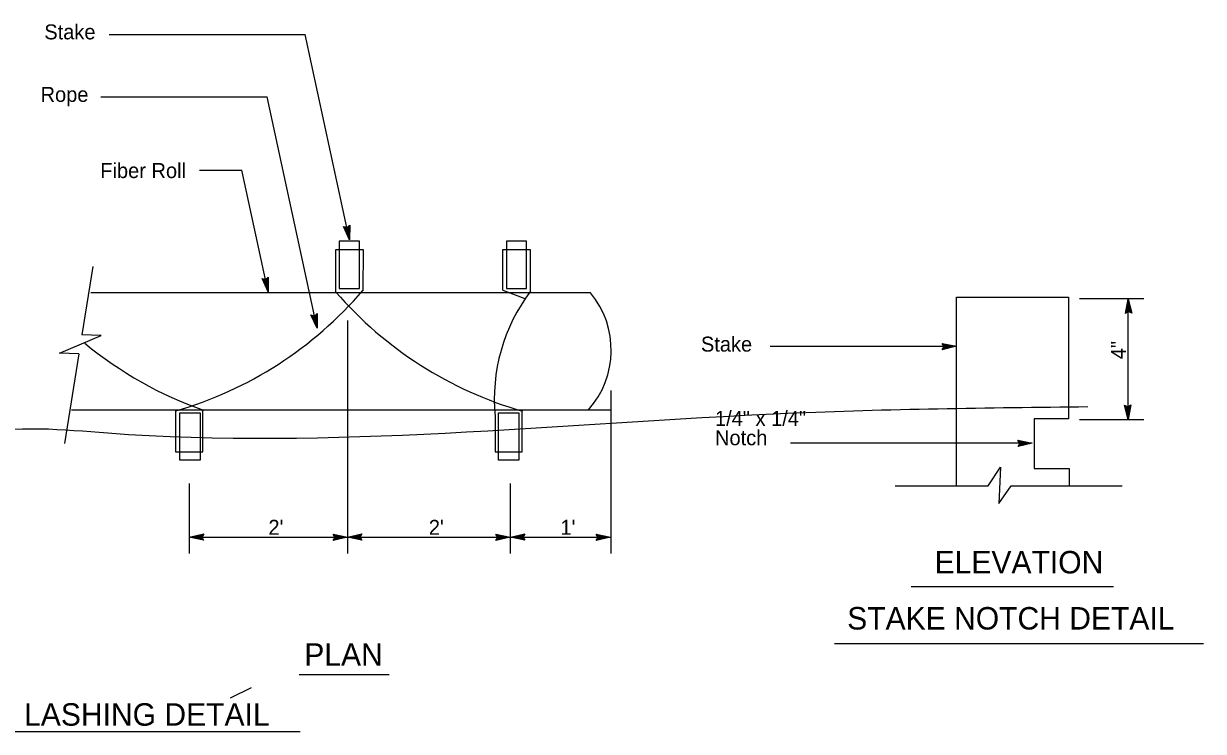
# Model space of a CAD drawing. Extents: x 6707415 to 6708768, y 1869893 to 1870831.
# Drawn here: x 6707688.3 to 6708160.7, y 1870548 to 1870831.3 of the extents above; entities that cross this region are included whole.
import ezdxf

# ---------------------------------------------------------------- set-up
doc = ezdxf.new("R2010")
doc.units = 0
for name, color, linetype in [('56 Stg 3 Anno', 7, 'Continuous'), ('57 Undefined', 7, 'Continuous'), ('60 Nongeo Data', 7, 'Continuous')]:
    doc.layers.add(name, color=color, linetype=linetype)

msp = doc.modelspace()

# ---------------------------------------------------------------- linework, layer by layer
at = {"layer": '56 Stg 3 Anno'}
for p, q in [((6707722.63, 1870827.01), (6707801.07, 1870827.01)), ((6707818.84, 1870744.79), (6707801.07, 1870827.01)), ((6707719.2, 1870801.99), (6707785.82, 1870801.99)), ((6707805.84, 1870709.37), (6707785.82, 1870801.99)), ((6707758.79, 1870772.63), (6707775.73, 1870772.63)), ((6707786.26, 1870723.94), (6707775.73, 1870772.63)), ((6707818.84, 1870744.79), (6707816.38, 1870750.15)), ((6707816.38, 1870750.15), (6707816.38, 1870750.15)), ((6707816.38, 1870750.15), (6707817.79, 1870749.67)), ((6707818.56, 1870746.1), (6707816.77, 1870750.01)), ((6707817.79, 1870749.67), (6707818.89, 1870750.69)), ((6707818.31, 1870750.13), (6707818.29, 1870747.39)), ((6707818.6, 1870750.42), (6707818.56, 1870746.09)), ((6707818.89, 1870750.69), (6707818.84, 1870744.79)), ((6707818.89, 1870750.69), (6707818.89, 1870750.69)), ((6707818.29, 1870747.39), (6707817.13, 1870749.91)), ((6707818.01, 1870748.68), (6707817.51, 1870749.76)), ((6707818.02, 1870749.89), (6707818.01, 1870748.68)), ((6707818.84, 1870744.79), (6707818.84, 1870744.79)), ((6707786.26, 1870723.94), (6707783.8, 1870729.3)), ((6707783.8, 1870729.3), (6707783.8, 1870729.3)), ((6707783.8, 1870729.3), (6707785.21, 1870728.82)), ((6707785.97, 1870725.24), (6707784.18, 1870729.15)), ((6707785.7, 1870726.53), (6707784.55, 1870729.06)), ((6707785.43, 1870727.83), (6707784.93, 1870728.91)), ((6707785.21, 1870728.82), (6707786.31, 1870729.84)), ((6707785.43, 1870729.04), (6707785.43, 1870727.83)), ((6707785.72, 1870729.27), (6707785.7, 1870726.53)), ((6707786.02, 1870729.57), (6707785.98, 1870725.23)), ((6707786.31, 1870729.84), (6707786.26, 1870723.94)), ((6707786.31, 1870729.84), (6707786.31, 1870729.84)), ((6707786.26, 1870723.94), (6707786.26, 1870723.94)), ((6708111.13, 1870721.29), (6708136.89, 1870721.29)), ((6708129.49, 1870715.26), (6708130.61, 1870721.06)), ((6708129.83, 1870715.48), (6708130.65, 1870719.73)), ((6708130.16, 1870715.72), (6708130.68, 1870718.41)), ((6708130.49, 1870715.89), (6708130.72, 1870717.08)), ((6708130.61, 1870672.85), (6708130.61, 1870721.06)), ((6708130.61, 1870721.06), (6708130.61, 1870721.06)), ((6708130.61, 1870721.06), (6708132.05, 1870715.34)), ((6708130.65, 1870719.72), (6708131.7, 1870715.55)), ((6708130.68, 1870718.41), (6708131.36, 1870715.71)), ((6708130.72, 1870717.08), (6708131.01, 1870715.93)), ((6707805.84, 1870709.37), (6707803.38, 1870714.73)), ((6707803.38, 1870714.73), (6707803.38, 1870714.73)), ((6707803.38, 1870714.73), (6707804.79, 1870714.25)), ((6707805.56, 1870710.68), (6707803.77, 1870714.59)), ((6707805.28, 1870711.97), (6707804.13, 1870714.49)), ((6707805.01, 1870713.26), (6707804.51, 1870714.34)), ((6707804.79, 1870714.25), (6707805.89, 1870715.27)), ((6707805.02, 1870714.47), (6707805.01, 1870713.26)), ((6707805.31, 1870714.71), (6707805.28, 1870711.97)), ((6707805.6, 1870715), (6707805.56, 1870710.67)), ((6707805.89, 1870715.27), (6707805.84, 1870709.37)), ((6707805.89, 1870715.27), (6707805.89, 1870715.27)), ((6707818.04, 1870712.48), (6707818.04, 1870619.14)), ((6708130.75, 1870716.07), (6708129.49, 1870715.26)), ((6708129.49, 1870715.26), (6708129.49, 1870715.26)), ((6708132.05, 1870715.34), (6708130.75, 1870716.07)), ((6708132.05, 1870715.34), (6708132.05, 1870715.34)), ((6707805.84, 1870709.37), (6707805.84, 1870709.37)), ((6708056.91, 1870702.01), (6708056.1, 1870703.27)), ((6708056.1, 1870703.27), (6708056.1, 1870703.27)), ((6708056.1, 1870703.27), (6708061.9, 1870702.15)), ((6708056.32, 1870702.94), (6708060.57, 1870702.12)), ((6707987.21, 1870702.15), (6708061.9, 1870702.15)), ((6708061.9, 1870702.15), (6708056.18, 1870700.71)), ((6708056.18, 1870700.71), (6708056.91, 1870702.01)), ((6708056.18, 1870700.71), (6708056.18, 1870700.71)), ((6708060.56, 1870702.11), (6708056.39, 1870701.06)), ((6708056.55, 1870702.6), (6708059.24, 1870702.08)), ((6708059.24, 1870702.08), (6708056.55, 1870701.4)), ((6708056.73, 1870702.27), (6708057.92, 1870702.04)), ((6708057.92, 1870702.04), (6708056.77, 1870701.75)), ((6708061.9, 1870702.15), (6708061.9, 1870702.15)), ((6707923.49, 1870684.37), (6707923.49, 1870619.14)), ((6708130.61, 1870672.85), (6708129.17, 1870678.57)), ((6708129.17, 1870678.57), (6708129.17, 1870678.57)), ((6708129.17, 1870678.57), (6708130.46, 1870677.84)), ((6708130.57, 1870674.19), (6708129.52, 1870678.36)), ((6708130.53, 1870675.5), (6708129.85, 1870678.2)), ((6708130.5, 1870676.83), (6708130.21, 1870677.98)), ((6708130.46, 1870677.84), (6708131.73, 1870678.65)), ((6708130.73, 1870678.02), (6708130.5, 1870676.83)), ((6708131.05, 1870678.2), (6708130.53, 1870675.5)), ((6708131.39, 1870678.43), (6708130.57, 1870674.18)), ((6708131.73, 1870678.65), (6708130.61, 1870672.85)), ((6708131.73, 1870678.65), (6708131.73, 1870678.65)), ((6708111.13, 1870672.85), (6708136.89, 1870672.85)), ((6708130.61, 1870672.85), (6708130.61, 1870672.85)), ((6708092.23, 1870663.4), (6707995.46, 1870663.4)), ((6708087.24, 1870663.25), (6708086.43, 1870664.52)), ((6708086.43, 1870664.52), (6708086.43, 1870664.52)), ((6708086.43, 1870664.52), (6708092.23, 1870663.4)), ((6708092.23, 1870663.4), (6708086.51, 1870661.96)), ((6708086.51, 1870661.96), (6708087.24, 1870663.25)), ((6708086.51, 1870661.96), (6708086.51, 1870661.96)), ((6708086.65, 1870664.18), (6708090.9, 1870663.36)), ((6708090.89, 1870663.36), (6708086.72, 1870662.31)), ((6708086.88, 1870663.84), (6708089.57, 1870663.32)), ((6708089.57, 1870663.32), (6708086.88, 1870662.64)), ((6708087.06, 1870663.52), (6708088.25, 1870663.29)), ((6708088.25, 1870663.29), (6708087.1, 1870663)), ((6708092.23, 1870663.4), (6708092.23, 1870663.4)), ((6707754.67, 1870647.14), (6707754.67, 1870619.14)), ((6707883.15, 1870647.14), (6707883.15, 1870619.14)), ((6707754.67, 1870625.78), (6707760.44, 1870627.03)), ((6707754.67, 1870625.78), (6707818.04, 1870625.78)), ((6707760.42, 1870624.47), (6707754.67, 1870625.78)), ((6707754.67, 1870625.78), (6707754.67, 1870625.78)), ((6707760.22, 1870624.81), (6707755.99, 1870625.77)), ((6707756.01, 1870625.78), (6707760.21, 1870626.69)), ((6707757.32, 1870625.76), (6707760.04, 1870626.35)), ((6707760, 1870625.16), (6707757.32, 1870625.76)), ((6707758.65, 1870625.76), (6707759.81, 1870626.01)), ((6707759.83, 1870625.49), (6707758.65, 1870625.76)), ((6707760.44, 1870627.03), (6707759.66, 1870625.76)), ((6707759.66, 1870625.76), (6707760.42, 1870624.47)), ((6707760.42, 1870624.47), (6707760.42, 1870624.47)), ((6707760.44, 1870627.03), (6707760.44, 1870627.03)), ((6707813.05, 1870625.63), (6707812.24, 1870626.9)), ((6707812.24, 1870626.9), (6707812.24, 1870626.9)), ((6707812.24, 1870626.9), (6707818.04, 1870625.78)), ((6707818.04, 1870625.78), (6707812.32, 1870624.33)), ((6707812.32, 1870624.33), (6707813.05, 1870625.63)), ((6707812.32, 1870624.33), (6707812.32, 1870624.33)), ((6707812.46, 1870626.56), (6707816.71, 1870625.74)), ((6707816.7, 1870625.74), (6707812.53, 1870624.69)), ((6707812.69, 1870626.22), (6707815.39, 1870625.7)), ((6707815.39, 1870625.7), (6707812.69, 1870625.02)), ((6707812.87, 1870625.89), (6707814.06, 1870625.67)), ((6707814.06, 1870625.67), (6707812.91, 1870625.37)), ((6707818.04, 1870625.78), (6707823.8, 1870627.03)), ((6707818.04, 1870625.78), (6707883.15, 1870625.78)), ((6707823.79, 1870624.47), (6707818.04, 1870625.78)), ((6707818.04, 1870625.78), (6707818.04, 1870625.78)), ((6707818.04, 1870625.78), (6707818.04, 1870625.78)), ((6707823.58, 1870624.81), (6707819.36, 1870625.77)), ((6707819.37, 1870625.78), (6707823.58, 1870626.69)), ((6707820.69, 1870625.76), (6707823.4, 1870626.35)), ((6707823.36, 1870625.16), (6707820.69, 1870625.76)), ((6707822.02, 1870625.76), (6707823.18, 1870626.01)), ((6707823.19, 1870625.49), (6707822.02, 1870625.76)), ((6707823.8, 1870627.03), (6707823.03, 1870625.76)), ((6707823.03, 1870625.76), (6707823.79, 1870624.47)), ((6707823.79, 1870624.47), (6707823.79, 1870624.47)), ((6707823.8, 1870627.03), (6707823.8, 1870627.03)), ((6707878.16, 1870625.63), (6707877.35, 1870626.9)), ((6707877.35, 1870626.9), (6707877.35, 1870626.9)), ((6707877.35, 1870626.9), (6707883.15, 1870625.78)), ((6707883.15, 1870625.78), (6707877.42, 1870624.33)), ((6707877.42, 1870624.33), (6707878.16, 1870625.63)), ((6707877.42, 1870624.33), (6707877.42, 1870624.33)), ((6707877.57, 1870626.56), (6707881.82, 1870625.74)), ((6707881.81, 1870625.74), (6707877.64, 1870624.69)), ((6707877.8, 1870626.22), (6707880.49, 1870625.7)), ((6707880.49, 1870625.7), (6707877.8, 1870625.02)), ((6707877.98, 1870625.89), (6707879.17, 1870625.67)), ((6707879.17, 1870625.67), (6707878.02, 1870625.37)), ((6707883.15, 1870625.78), (6707883.15, 1870625.78)), ((6707883.24, 1870625.78), (6707889.01, 1870627.03)), ((6707883.24, 1870625.78), (6707923.34, 1870625.78)), ((6707889, 1870624.47), (6707883.24, 1870625.78)), ((6707883.24, 1870625.78), (6707883.24, 1870625.78)), ((6707888.79, 1870624.81), (6707884.57, 1870625.77)), ((6707884.58, 1870625.78), (6707888.78, 1870626.69)), ((6707885.9, 1870625.76), (6707888.61, 1870626.35)), ((6707888.57, 1870625.16), (6707885.9, 1870625.76)), ((6707887.22, 1870625.76), (6707888.38, 1870626.01)), ((6707888.4, 1870625.49), (6707887.22, 1870625.76)), ((6707889.01, 1870627.03), (6707888.24, 1870625.76)), ((6707888.24, 1870625.76), (6707889, 1870624.47)), ((6707889, 1870624.47), (6707889, 1870624.47)), ((6707889.01, 1870627.03), (6707889.01, 1870627.03)), ((6707918.35, 1870625.63), (6707917.54, 1870626.9)), ((6707917.54, 1870626.9), (6707917.54, 1870626.9)), ((6707917.54, 1870626.9), (6707923.34, 1870625.78)), ((6707923.34, 1870625.78), (6707917.62, 1870624.33)), ((6707917.62, 1870624.33), (6707918.35, 1870625.63)), ((6707917.62, 1870624.33), (6707917.62, 1870624.33)), ((6707917.76, 1870626.56), (6707922.01, 1870625.74)), ((6707922, 1870625.74), (6707917.83, 1870624.69)), ((6707920.69, 1870625.7), (6707917.99, 1870625.02)), ((6707918, 1870626.22), (6707920.69, 1870625.7)), ((6707918.17, 1870625.89), (6707919.36, 1870625.67)), ((6707919.36, 1870625.67), (6707918.21, 1870625.37)), ((6707923.34, 1870625.78), (6707923.34, 1870625.78))]:
    msp.add_line(p, q, dxfattribs=at)
at = {"layer": '57 Undefined'}
for p, q in [((6707707.5, 1870676.68), (6707923.6, 1870676.68)), ((6708043.74, 1870605.96), (6708124.8, 1870605.96)), ((6708012.97, 1870583.14), (6708160.74, 1870583.14)), ((6707798.64, 1870570.79), (6707834.7, 1870570.79)), ((6707596.65, 1870547.96), (6707799.02, 1870547.96))]:
    msp.add_line(p, q, dxfattribs=at)
at = {"layer": '60 Nongeo Data'}
for p, q in [((6707716.04, 1870734.04), (6707711.65, 1870706.73)), ((6707915.37, 1870723.52), (6707715.19, 1870723.52)), ((6707880.27, 1870724.54), (6707889, 1870721.24)), ((6707710.43, 1870699.14), (6707704.66, 1870663.25)), ((6707707.5, 1870676.68), (6707914.49, 1870676.68)), ((6708092.93, 1870673.08), (6708092.93, 1870653.25)), ((6708106.76, 1870673.08), (6708092.93, 1870673.08)), ((6708092.93, 1870653.25), (6708107.05, 1870653.25)), ((6708037.33, 1870646.21), (6708074.57, 1870646.21)), ((6708083.72, 1870646.21), (6708128.25, 1870646.21)), ((6707779.4, 1870565.46), (6707771.02, 1870561.28))]:
    msp.add_line(p, q, dxfattribs=at)
for points in [[(6707813.34, 1870723.87), (6707813.33, 1870740.84), (6707824.23, 1870740.84), (6707824.22, 1870724.38)], [(6707880.27, 1870724.54), (6707880.26, 1870740.9), (6707891.16, 1870740.9), (6707891.15, 1870724.23)], [(6708061.9, 1870721.79), (6708106.67, 1870721.79), (6708106.76, 1870673.08)], [(6708061.9, 1870646.21), (6708061.9, 1870721.79)], [(6707710.43, 1870699.14), (6707702.69, 1870699.41), (6707719.39, 1870706.46), (6707711.65, 1870706.73)], [(6707749.21, 1870676.27), (6707749.21, 1870659.83), (6707760.11, 1870659.83), (6707760.11, 1870676.27)], [(6707877.12, 1870674.05), (6707877.12, 1870659.83), (6707888.02, 1870659.83), (6707888.02, 1870676.04)], [(6708074.57, 1870646.21), (6708079.44, 1870653.71), (6708078.88, 1870639.22), (6708083.72, 1870646.21)], [(6708107.05, 1870653.25), (6708107.05, 1870646.21)]]:
    msp.add_lwpolyline(points, dxfattribs=at)
for points in [[(6707814.73, 1870725.23), (6707822.82, 1870725.23), (6707822.82, 1870744.16), (6707814.73, 1870744.16)], [(6707881.67, 1870725.29), (6707889.76, 1870725.29), (6707889.76, 1870744.23), (6707881.67, 1870744.23)], [(6707750.87, 1870675.44), (6707758.96, 1870675.44), (6707758.96, 1870656.5), (6707750.87, 1870656.5)], [(6707878.53, 1870675.44), (6707886.61, 1870675.44), (6707886.61, 1870656.5), (6707878.53, 1870656.5)]]:
    msp.add_lwpolyline(points, close=True, dxfattribs=at)
for centre, radius, start, end in [((6707705.78, 1870826.21), 156.11, 286.1553, 319.3308), ((6707931.22, 1870826.21), 156.11, 220.9637, 253.955), ((6707948.56, 1870680.88), 71.77, 142.9134, 185.463), ((6707887.63, 1870700.62), 35.98, 318.2932, 39.5418), ((6707812.13, 1870823.81), 156.11, 230.5092, 250.6348)]:
    msp.add_arc(centre, radius, start, end, dxfattribs=at)
msp.add_spline([(6707636.01, 1870722.73), (6707631.26, 1870703.25), (6707638.65, 1870677.44), (6707649.72, 1870664.81), (6707666.6, 1870666.39), (6707721.99, 1870667.44), (6707994.19, 1870675.34), (6708114.47, 1870677.97)], degree=3, dxfattribs=at)

# ---------------------------------------------------------------- texts
at = {"layer": '57 Undefined'}
for s, height, p in [('Stake', 6, (6707696.61, 1870825)), ('Rope', 6, (6707695.11, 1870799.98)), ('Fiber Roll', 6, (6707719.02, 1870769.48)), ('Stake', 6, (6707959.54, 1870700)), ('1/4" x 1/4"', 6, (6707965.17, 1870670.28)), ('Notch', 6, (6707965.17, 1870662.52)), ("2'", 6, (6707786.35, 1870626.66)), ("2'", 6, (6707850.59, 1870626.66)), ("1'", 6, (6707903.29, 1870626.66)), ('ELEVATION', 9, (6708053.11, 1870611.2)), ('STAKE NOTCH DETAIL', 9, (6708018.1, 1870588.74)), ('PLAN', 9, (6707800.71, 1870574.24)), ('STAKING AND LASHING DETAIL', 9, (6707603.59, 1870550.24))]:
    msp.add_text(s, height=height, dxfattribs=at).set_placement(p)
msp.add_text('4"', height=6, rotation=90, dxfattribs=at).set_placement((6708129.73, 1870696.96))

doc.saveas('drawing.dxf')
